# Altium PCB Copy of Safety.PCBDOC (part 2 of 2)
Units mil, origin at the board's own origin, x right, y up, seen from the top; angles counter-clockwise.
Board outline 11000 x 3900 mil, 4 copper layers (Top Layer, Grounds, +5V, Bottom Layer); 225 components, 170 nets, 779 pads, 129 vias.
Unrouted connection lines stored in the file: 11.
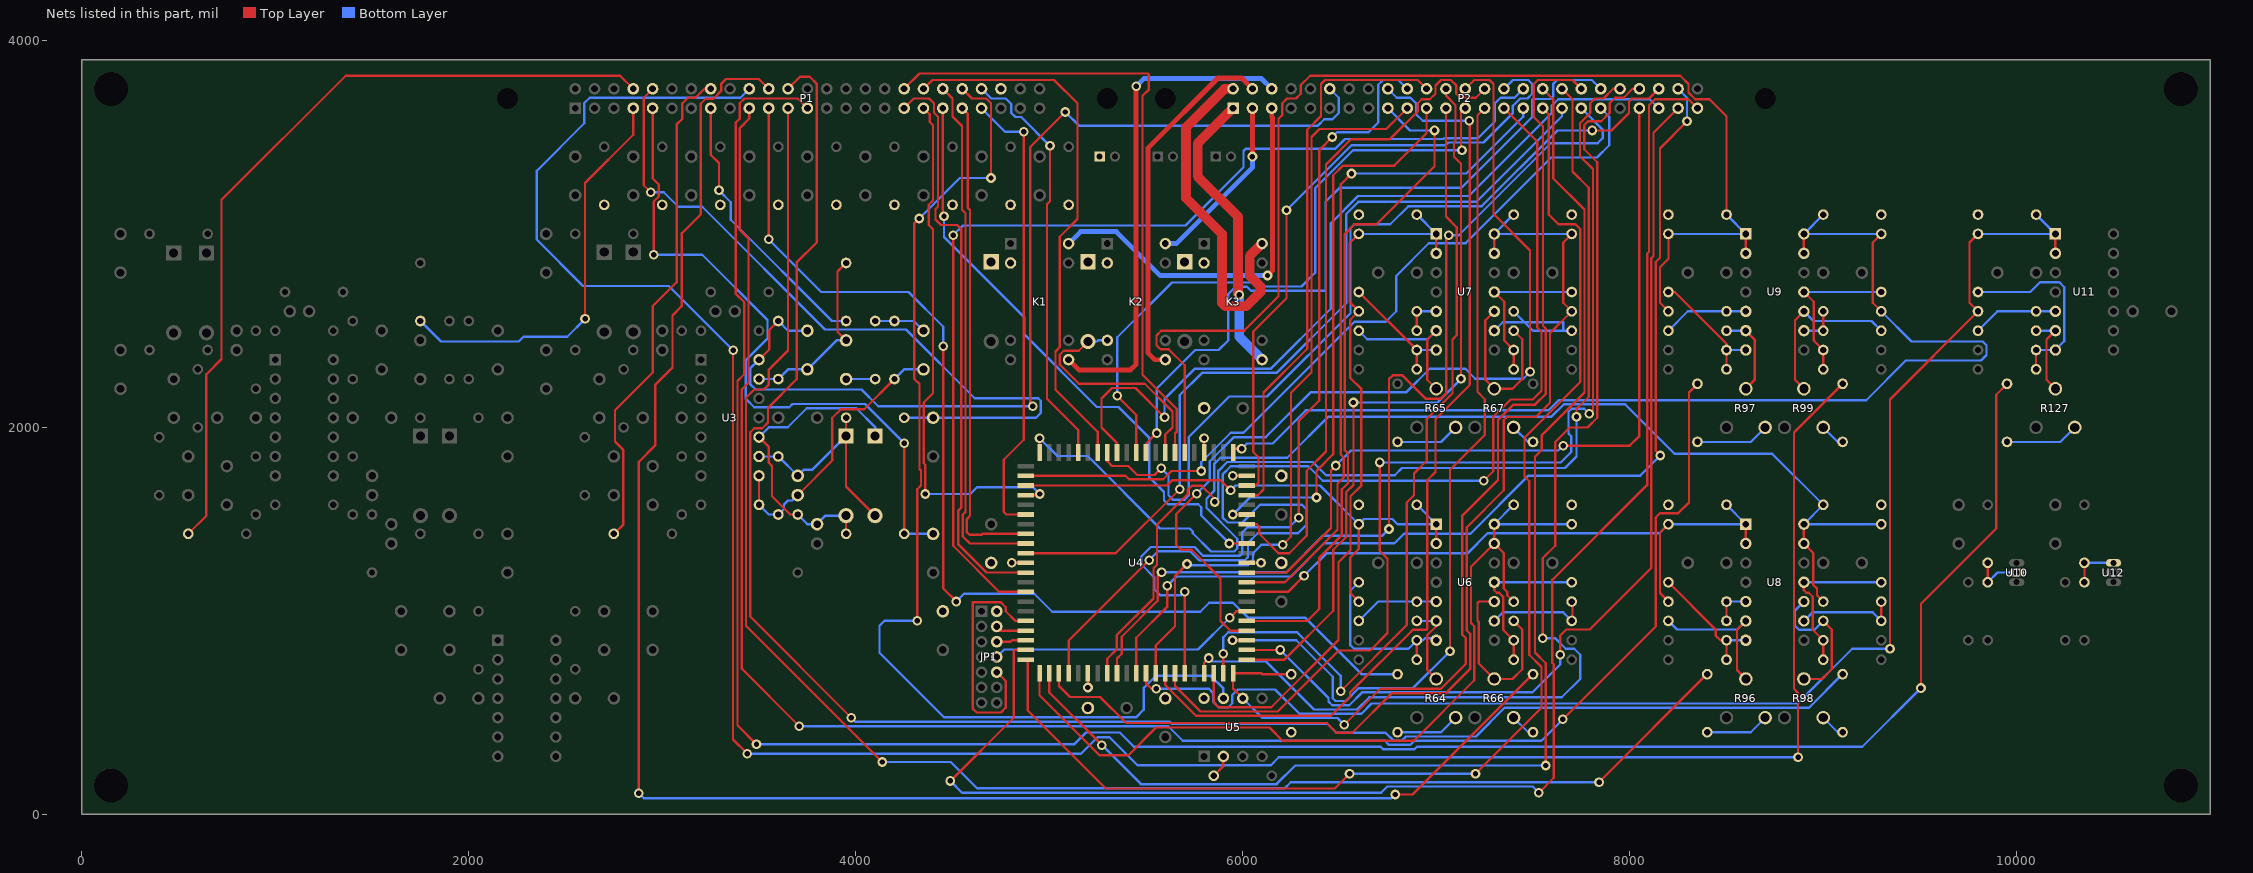
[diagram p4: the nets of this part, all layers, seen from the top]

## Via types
v1: diameter 50, hole 28, Top Layer to Bottom Layer, 129 vias

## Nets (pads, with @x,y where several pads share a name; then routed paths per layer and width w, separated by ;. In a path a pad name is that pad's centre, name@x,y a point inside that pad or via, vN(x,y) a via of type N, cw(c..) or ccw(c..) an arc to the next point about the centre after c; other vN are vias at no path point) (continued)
NetC36_1: C36.1 D7.2 D8.1 R34.1 R40.1 U3.9 | length 1144.7
  Top Layer w12: R40.1@3950,2050 D7.2@3950,1955.91 3950,1694.09 D8.1@4100,1544.09
  Bottom Layer w12: U3.9@3500,1850 R34.1@3600,1850 C36.1@3700,1750 3732,1782 3776.09,1782 D7.2@3950,1955.91
NetC36_2: C36.2 C44.1 R30.1 R34.2 R43.1 U3.8 | length 1473.9
  Top Layer w12: R30.1@3500,1600 U3.8@3500,1750 ; C36.2@3700,1650 3879,1829 3879,2050 3923,2094 4044,2094 R43.1@4200,2250
  Bottom Layer w12: R30.1@3500,1600 3550,1550 R34.2@3600,1550 3629.17,1579.17 3629.17,1601.41 3650,1622.25 3672.25,1622.25 C36.2@3700,1650 ; R43.1@4200,2250 4250,2300 C44.1@4350,2300
NetC37_1: C37.1 C40.2 R36.1 R41.2 U3.13 | length 969.3
  Top Layer w12: C40.2@3950,2450 3906,2494 3906,2806 R41.2@3950,2850
  Bottom Layer w12: U3.13@3500,2250 R36.1@3600,2250 3650,2300 C37.1@3750,2300 3900,2450 C40.2@3950,2450
NetC37_2: C37.2 P2.12 R36.2 U3.14 | length 5279.1
  Top Layer w12: U3.14@3500,2350 3553,2403 3553,2503 R36.2@3600,2550 ; v1(4915,2110) 4901,2124 4901,3448 v1(5083,3630)
  Bottom Layer w12: U3.14@3500,2350 3454,2304 3454,2225 3483,2196 4030.12,2196 4116.12,2110 v1(4915,2110) ; R36.2@3600,2550 3650,2500 C37.2@3750,2500 ; v1(5083,3630) 5153.16,3559.84 6388.58,3559.84 6421.58,3592.84 6463.84,3592.84 6496,3625 6496,3704 P2.12@6450,3750
NetC39_1: C39.1 D7.1 D8.2 R35.1 R39.1 U3.10 | length 1636.3
  Top Layer w12: U3.10@3500,1950 3551,1899 3551,1817.53 3567.53,1801 3567.53,1644.3 3661.83,1550 R35.1@3700,1550 ; R39.1@3950,1450 D7.1@3950,1544.09
  Bottom Layer w12: U3.10@3500,1950 3551,2001 3649,2001 3747,2099 4003,2099 4100,2002 D8.2@4100,1955.91 ; R35.1@3700,1550 3750,1500 C39.1@3800,1500 3844.09,1544.09 D7.1@3950,1544.09
NetC40_1: C40.1 R42.2 | length 150
  Bottom Layer w12: C40.1@3950,2250 R42.2@4100,2250
NetC42_1: C42.1 P1.9 R39.2 | length 3508.9
  Top Layer w12: P1.9@2950,3650 2950,3288 2982,3256 2982,3194.04 2956,3168.04 v1(2956,2892) ; R39.2@4250,1450 v1(4250,1919)
  Bottom Layer w12: v1(2956,2892) 3207,2892 3544,2555 3544,2460 3432,2348 3432,2147.47 3475,2104.47 3656.47,2104.47 3673,2121 4048,2121 v1(4250,1919) ; R39.2@4250,1450 C42.1@4400,1450
NetC43_1: C43.1 P1.10 R40.2 | length 3809.6
  Top Layer w12: v1(2941,3215) 2904,3252 2904,3704 P1.10@2950,3750
  Bottom Layer w12: v1(2941,3215) 3008,3215 3082.92,3140.08 3206.92,3140.08 3841,2506 4260,2506 4615,2151 4942.5,2151 4956,2137.5 4956,2075 4931,2050 C43.1@4400,2050 R40.2@4250,2050
NetC44_2: C44.2 R42.1 R43.2 | length 270.7
  Bottom Layer w12: R42.1@4100,2550 R43.2@4200,2550 4300,2550 C44.2@4350,2500
NetK1_8: K1.8 P2.6 | length 2559.5
  Top Layer w25: K1.8@5100,2350 5153,2297 5420,2297 5449,2326 v1(5449,3763)
  Bottom Layer w25: v1(5449,3763) 5489,3803 6097,3803 P2.6@6150,3750
NetK1_14: K1.14 P2.5 | length 2024.3
  Top Layer w25: v1(6128,2785) 6153,2810 6153,3603 6150,3606 P2.5@6150,3650
  Bottom Layer w25: K1.14@5100,2950 5162,3012 5347,3012 5574,2785 v1(6128,2785)
NetK2_8: K2.8 P2.4 | length 1876.2
  Top Layer w25: K2.8@5600,2350 5544.42,2350 5511,2383.42 5511,3445 5872,3806 5994,3806 P2.4@6050,3750
NetK2_14: K2.14 P2.3 | length 920
  Top Layer w25: v1(6050,3400) P2.3@6050,3650
  Bottom Layer w25: K2.14@5600,2950 5657.45,2950 6050,3342.55 v1(6050,3400)
NetK3_8: K3.8 P2.1 | length 1513.7
  Top Layer w50: P2.1@5950,3650 5767,3467 5767,3297.96 5975.47,3089.49 5975.47,2692.53 v1(5982,2686)
  Bottom Layer w50: v1(5982,2686) 5982,2468 K3.8@6100,2350
NetK3_14: K3.14 P2.2 | length 1847.3
  Top Layer w50: P2.2@5950,3750 5906,3750 5707,3551 5707,3186 5893,3000 5893,2643 5910,2626 6018,2626 6092,2700 6092,2728.47 6035.47,2785 6035.47,2885.47 K3.14@6100,2950
NetP1_7: P1.7 R16.1 | length 2135.5
  Top Layer w12: v1(2601,2561) 2601,3264 2850,3513 P1.7@2850,3650
  Bottom Layer w12: R16.1@1750,2550 1856,2444 2258,2444 2283,2469 2509,2469 v1(2601,2561)
NetP1_8: P1.8 R4.1 | length 4219.3
  Top Layer w12: R4.1@550,1450 644,1544 644,2275 722.37,2353.37 722.37,3176.37 1364,3818 2782,3818 P1.8@2850,3750
NetP1_15: P1.15 R41.1 | length 1432.7
  Top Layer w12: P1.15@3250,3650 3250,3409 3293,3366 v1(3293,3225)
  Bottom Layer w12: v1(3293,3225) 3354,3164 3354,3073 3877,2550 R41.1@3950,2550
NetP1_16: P1.16 R25.1 | length 2584.3
  Top Layer w12: R25.1@2750,1450 2799,1499 2799,1884 2756,1927 2756,2089 2951,2284 2951,2627 3074,2750 3074,3565 3104,3595 3104,3675 3133,3704 3172,3704 3218,3750 P1.16@3250,3750
NetP1_19: P1.19 R95.1 | length 9488.3
  Top Layer w12: P1.19@3450,3650 3450,3596.85 3401,3547.85 3401,3021 3445.48,2976.52 3445.48,2230.54 3410.47,2195.53 3410.47,753.53 v1(3708,456) ; v1(7654,491) 8134,971 8134,1534 8156,1556 8250,1556 8306,1612 8306,2181 R95.1@8350,2225
  Bottom Layer w12: v1(3708,456) 5615,456 5690,381 6734.44,381 6756,359.44 6865.56,359.44 6887.12,381 7544,381 v1(7654,491)
NetP1_20: P1.20 R111.1 | length 12644.1
  Top Layer w12: v1(3366,2399) 3366,387 v1(3440,313) ; v1(8870,295) 8870,628 8849,649 8849,1974 R111.1@9100,2225
  Bottom Layer w12: v1(3366,2399) 3033.91,2731.09 2590.91,2731.09 2351,2971 2351,3326 2597,3572 2597,3676 2625,3704 3404,3704 P1.20@3450,3750 ; v1(3440,313) 5164,313 5250,399 5311.5,399 5456.03,254.47 6146,254.47 6186.53,295 v1(8870,295)
NetP1_21: P1.21 R63.1 | length 5722.7
  Top Layer w12: v1(3550,2972) P1.21@3550,3650 ; v1(4452,2420) 4452,1168 v1(4520,1100)
  Bottom Layer w12: v1(3550,2972) 3822,2700 4272,2700 4452,2520 v1(4452,2420) ; v1(4520,1100) 4560,1140 4922.54,1140 5015.44,1047.1 5780.1,1047.1 5827,1094 5950,1094 6027,1017 6321.4,1017 6613.4,725 R63.1@6800,725
NetP1_22: P1.22 R78.1 | length 9039.1
  Top Layer w12: v1(2879,110) 2879,1823 2963,1907 2963,2220 3053,2310 3053,2579 3101,2627 3101,3003 3199,3101 3199,3673 3225,3699 3264.05,3699 3304,3738.95 3304,3775 3330,3801 3499,3801 P1.22@3550,3750 ; v1(6788,103) 6878,103 R78.1@7500,725
  Bottom Layer w12: v1(2879,110) 2905,84 6769,84 v1(6788,103)
NetP1_23: P1.23 R94.1 | length 8354.4
  Top Layer w12: P1.23@3650,3650 3650,2398 3551,2299 3551,2222 3525,2196 3475,2196 3432.47,2153.47 3432.47,975.53 v1(4136.95,271.05) ; v1(7841.61,166.61) R94.1@8400,725
  Bottom Layer w12: v1(4136.95,271.05) 4491.11,271.05 4627.72,134.44 6215.56,134.44 6247.73,166.61 v1(7841.61,166.61)
NetP1_24: P1.24 R110.1 | length 9163.2
  Top Layer w12: P1.24@3650,3750 3712,3812 3762,3812 3799,3775 3799,2957 3694.38,2852.38 3694.38,2249.38 3546,2101 3546,2025 3517,1996 3475,1996 3454.47,1975.47 3454.47,1022.53 v1(3977,500)
  Bottom Layer w12: v1(3977,500) 3997.48,479.52 5622.6,479.52 5633.11,469 6437,469 6484,422 6738,422 6778.56,381.44 6821.44,381.44 6843,403 7205,403 7353,551 8926,551 R110.1@9100,725
NetP1_25: P1.25 R126.1 | length 11742.6
  Top Layer w12: v1(3487,362) 3388.47,460.53 3388.47,2239.53 3423.48,2274.54 3423.48,2648 3379,2692.48 3379,3575 3400,3596 3400,3675 3425,3700 3700,3700 P1.25@3750,3650 ; v1(9505,653) 9505,1089 9894,1478 9894,2169 R126.1@9950,2225
  Bottom Layer w12: v1(3487,362) 5128,362 5189.39,423.39 5364,423.39 5437.39,350 6712.44,350 6725,337.44 6887.56,337.44 6900.12,350 9202,350 v1(9505,653)
NetP1_35: P1.35 U4.23 | length 2997.1
  Top Layer w12: P1.35@4250,3650 4300,3700 4379,3700 4404,3675 4404,3626.5 4425,3605.5 4425,3140.94 4412.5,3128.44 4412.5,3075 4441.06,3046.44 4523.56,3046.44 4545,3025 4545,1585.65 4530.22,1570.87 4530.22,1395.26 4675.49,1250 U4.23@4879.13,1250
NetP1_36: P1.36 U4.81 | length 3343.7
  Top Layer w12: P1.36@4250,3750 4329,3829 5510.02,3829 5515,3824.02 5515,3747 5482,3714 5482,2272 5659,2095 5659,1978.29 5650,1969.29 U4.81@5650,1870.87
NetP1_37: P1.37 U4.15 | length 2751.1
  Top Layer w12: P1.37@4350,3650 4382,3618 4382,3578.5 4399,3561.5 4399,3172.44 4377,3150.44 4377,3046.44 4399,3024.44 4399,2177 4351,2129 4351,1815 4359,1807 v1(4359,1656) ; U4.15@4879.13,1650 4945,1650 v1(4951,1656)
  Bottom Layer w12: v1(4359,1656) 4592,1656 4627,1691 4916,1691 v1(4951,1656)
NetP1_38: P1.38 U4.5 | length 2806.4
  Top Layer w12: P1.38@4350,3750 4396,3796 5025,3796 5146,3675 5146,3077 5054.47,2985.47 5054.47,2415 5032.47,2393 5032.47,2195 5250,1977.47 U4.5@5250,1870.87
NetP1_39: P1.39 U4.66 | length 3110.5
  Top Layer w12: P1.39@4450,3650 4450,3098 v1(4456,3092) ; v1(5931,1400) U4.66@6020.87,1400
  Bottom Layer w12: v1(4456,3092) 4456,2984 4871.59,2568.41 4871.59,2480.41 5246,2106 5357.84,2106 5516,1947.83 5516,1744 5593,1667 5593,1624 5614,1603 5770.5,1603 5786,1587.5 5786,1545 v1(5931,1400)
NetP1_40: P1.40 U4.20 | length 2709.5
  Top Layer w12: P1.40@4450,3750 4500,3700 4500,3607 4549,3558 4549,3125 4567,3107 4567,1563.65 4552.22,1548.87 4552.22,1437.5 4589.72,1400 U4.20@4879.13,1400
NetP1_41: P1.41 U4.19 | length 2528
  Top Layer w12: P1.41@4550,3650 4578,3622 4578,3136 4590.62,3123.38 4590.62,1543.27 4574.22,1526.87 4574.22,1458.15 4587.5,1444.87 4651.09,1444.87 4656.22,1450 U4.19@4879.13,1450
NetP1_42: P1.42 U5.7 | length 5628.6
  Top Layer w12: v1(4318,1001) 4318,1681 4337,1700 4337,1777 4329,1785 4329,2224.52 4301.52,2252 4301.52,3053.52 v1(4328,3080) ; P1.42@4550,3750 4600,3700 4674,3700 4699,3675 v1(4699,3289)
  Bottom Layer w12: v1(4318,1001) 4149,1001 4123,975 4123,836 4457.48,501.52 5448,501.52 5488,541.52 5488,654 5550,716 5834,716 5900,650 U5.7@5900,600 ; v1(4328,3080) 4537,3289 v1(4699,3289)
NetP1_43: P1.43 U4.17 | length 2395.9
  Top Layer w12: v1(4868,3528) 4868,1936 4764.83,1832.83 4764.83,1563.17 4778,1550 U4.17@4879.13,1550
  Bottom Layer w12: P1.43@4650,3650 4772,3528 v1(4868,3528)
NetP1_44: P1.44 U4.7 | length 2161
  Top Layer w12: v1(5004,3455) 5004,3169 4988,3153 4988,2148 5150,1986 U4.7@5150,1870.87
  Bottom Layer w12: P1.44@4650,3750 4700,3700 4775,3700 4804,3671 4804,3625 4825,3604 4855,3604 v1(5004,3455)
NetP2_17: P2.17 U4.58 | length 3487.8
  Top Layer w12: U4.58@6020.87,1000 6333,1000 6396,1063 6396,1327.23 6512.44,1443.67 6512.44,1680 6544,1711.56 6544,1866 6528,1882 6528,3000 6578,3050 6691,3050 6991,3350 v1(6991,3535)
  Bottom Layer w12: P2.17@6750,3650 6865,3535 v1(6991,3535)
NetP2_18: P2.18 U4.46 | length 4920
  Top Layer w12: U4.46@5600,729.13 5600,668.56 5758.56,510 6456.19,510 6554.19,608 6554.19,629.76 6879.32,954.89 6950.77,954.89 6954,958.11 6954,1727 6996,1769 6996,2042.1 7174,2220.1 7174,3582 v1(7171,3585)
  Bottom Layer w12: P2.18@6750,3750 6796,3704 6867,3704 6896,3675 6896,3619 6930,3585 v1(7171,3585)
NetP2_19: P2.19 U4.45 | length 3919.7
  Top Layer w12: U4.45@5550,729.13 5550,873 5650,973 5650,1232 v1(5712,1294) ; v1(6206,1393) 6248,1435 6248,1535 6249,1536 6249,2179 6355,2285 6355,3501 6396,3542 6742,3542 P2.19@6850,3650
  Bottom Layer w12: v1(5712,1294) 5719,1287 6025,1287 6053,1315 6053,1350 6096,1393 v1(6206,1393)
NetP2_20: P2.20 U4.48 | length 4476.5
  Top Layer w12: U4.48@5700,729.13 v1(5700,1150) ; v1(6290,1534) 6290,2035 6396,2141 6396,3434 v1(6463,3501)
  Bottom Layer w12: v1(5700,1150) 5682,1132 5575,1132 5543,1164 5543,1225 5475,1293 5475,1332.5 5524.5,1382 5750,1382 5796,1336 5984,1336 5998,1350 5998,1458 6024,1484 6240,1484 v1(6290,1534) ; v1(6463,3501) 6487.5,3525.5 6650,3525.5 6700,3575.5 6700,3771 6725,3796 6804,3796 P2.20@6850,3750
NetP2_21: P2.21 U4.69 | length 2943.4
  Top Layer w12: v1(5949,1550) U4.69@6020.87,1550 ; v1(6381,1638) 6381,1775 6468,1862 6468,3303.22 6517.78,3353 6783,3353 6950,3520 P2.21@6950,3650
  Bottom Layer w12: v1(5949,1550) 6037,1638 v1(6381,1638)
NetP2_22: P2.22 U4.71 | length 2890.9
  Top Layer w12: U4.71@6020.87,1650 6078,1650 6107,1679 6107,2181 6333,2407 6333,3539 6404,3610 6404,3775 6425,3796 6904,3796 P2.22@6950,3750
NetP2_23: P2.23 U4.52 | length 4260.1
  Top Layer w12: U4.52@5900,729.13 v1(5900,831) ; v1(6506,637) 6848,979 6848,1612 6885,1649 6885,1762 6951,1828 6951,2043.89 7084,2176.89 7084,2455 7106,2477 7106,3034 7050,3090 P2.23@7050,3650
  Bottom Layer w12: v1(5900,831) 5900,916 5925,941 6281,941 6506,716 v1(6506,637)
NetP2_24: P2.24 U4.54 | length 3816
  Top Layer w12: U4.54@6020.87,800 6215.59,800 6468,1052.41 6468,1367.82 6534.44,1434.26 6534.44,1665.56 6572,1703.12 v1(6572,2129) ; P2.24@7050,3750 7050,3715.05 7100,3665.05 7100,3480.93 7091.74,3472.68 7091.74,3398.93 7128,3362.68 v1(7128,2251)
  Bottom Layer w12: v1(6572,2129) 7006,2129 v1(7128,2251)
NetP2_25: P2.25 U4.1 | length 3320.8
  Top Layer w12: v1(5351,2163) 5450,2064 U4.1@5450,1870.87 ; v1(7133,3432) 7128,3437 7128,3628 P2.25@7150,3650
  Bottom Layer w12: v1(5351,2163) 5351,2466 5634,2749 6062.82,2749 6083.82,2728 6303,2728 6375,2800 6375,3237 6570,3432 v1(7133,3432)
NetP2_26: P2.26 U4.57 | length 4809.1
  Top Layer w12: v1(5762,1658) 5656.07,1552.07 5656.07,1393.22 5681.36,1367.92 5735.92,1367.92 5885,1218.85 5885,1000 5935,950 U4.57@6020.87,950 ; P2.26@7150,3750 7196,3796 7275,3796 7296,3775 7296,3104 7485,2915 v1(7485,2287)
  Bottom Layer w12: v1(5762,1658) 5830,1726 5830,1825 5955,1950 6119,1950 6350,2181 6844,2181 6966,2303 7151,2303 7202,2252 7450,2252 v1(7485,2287)
NetP2_27: P2.27 U4.56 | length 4412.3
  Top Layer w12: v1(5947,900) U4.56@6020.87,900 ; v1(7071,843.51) 7071,1781.37 7251,1961.37 7251,2146 7213,2184 7213,3613 P2.27@7250,3650
  Bottom Layer w12: v1(5947,900) 6276.93,900 6465,711.93 6465,600 6479,586 6533,586 6599.71,652.71 6880.2,652.71 v1(7071,843.51)
NetP2_28: P2.28 U4.68 | length 3522.9
  Top Layer w12: U4.68@6020.87,1500 6072.5,1500 6085,1487.5 6085,1450 6185,1350 6240,1350 6331,1441 6331,1776 6430,1875 6430,3359 6561,3490 6761,3490 6904,3633 6904,3675 6925,3696 6967,3696 6996,3725 6996,3767 7025,3796 7075,3796 7104,3767 7104,3725 7125,3704 7204,3704 P2.28@7250,3750
NetP2_29: P2.29 U4.36 | length 6116.6
  Top Layer w12: U4.36@5100,729.13 5100,898 v1(5516,1314) ; v1(7246,1724) 7295,1773 7295,2054.8 7384.83,2144.63 7498.75,2144.63 7544,2189.88 7544,2495.02 7522,2517.02 7522,3478 P2.29@7350,3650
  Bottom Layer w12: v1(5516,1314) 5562,1360 5728,1360 5774,1314 6010,1314 6027,1331 6027,1402 6078,1453 6286,1453 6331,1498 6331,1574.97 6304.97,1601 6090,1601 5998,1509 5922,1509 5896,1535 5896,1756.89 5938.11,1799 6339,1799 6414,1724 v1(7246,1724)
NetP2_30: P2.30 U4.72 | length 3321.7
  Top Layer w12: U4.72@6020.87,1700 6067.25,1700 6081,1713.75 6081,1845.74 6054,1872.74 6054,2496 6226,2668 v1(6226,3121.98)
  Bottom Layer w12: v1(6226,3121.98) 6562.02,3458 7047.74,3458 7062.74,3473 7244,3473 7396,3625 7396,3662 7434,3700 7471,3700 7496,3725 7496,3775 7475,3796 7396,3796 P2.30@7350,3750
NetP2_31: P2.31 U4.62 | length 3518.6
  Top Layer w12: U4.62@6020.87,1200 6218.32,1200 6490,1471.68 6490,1709.12 6522,1741.12 6522,1844 6506,1860 6506,3256 v1(6562,3312)
  Bottom Layer w12: v1(6562,3312) 7155.6,3312 7450,3606.4 P2.31@7450,3650
NetP2_32: P2.32 U4.25 | length 5442.4
  Top Layer w12: v1(4504,2994) 4504,1388 4742,1150 U4.25@4879.13,1150
  Bottom Layer w12: v1(4504,2994) 4554,3044 5703.73,3044 6003.95,3344.21 6003.95,3428 6016.95,3441 6479.02,3441 6529.02,3491 7036.74,3491 7040.74,3495 7216,3495 7303,3582 7303,3675 7332,3704 7404,3704 P2.32@7450,3750
NetP2_33: P2.33 U4.32 | length 6653.6
  Top Layer w12: U4.32@4879.13,800 4889,800 4889,537 5292,134 6476,134 v1(6552,210) ; v1(7203,210) 7544,551 7544,762 7481,825 7481,1722 7456,1747 7456,1947 7744,2235 7744,3025 7719,3050 7632,3050 7582,3100 7582,3618 P2.33@7550,3650
  Bottom Layer w12: v1(6552,210) v1(7203,210)
NetP2_34: P2.34 U4.34 | length 6617
  Top Layer w12: U4.34@5000,729.13 5000,630 v1(5272,358) ; P2.34@7550,3750 7604,3696 7604,3288 7766,3126 7766,2181 7546,1961 7546,1884.84 7510,1848.84 7510,837 7566,781 v1(7566,253)
  Bottom Layer w12: v1(5272,358) 5473.56,156.44 6175,156.44 6271.56,253 v1(7566,253)
NetP2_35: P2.35 U4.21 | length 4302.9
  Top Layer w12: U4.21@4879.13,1350 5343,1350 v1(5674,1681)
  Bottom Layer w12: v1(5674,1681) 5674,2167 5789,2282 6175,2282 6534.44,2641.44 6534.44,3103 6597,3165.56 7207,3165.56 7650,3608.56 P2.35@7650,3650
NetP2_36: P2.36 U4.40 | length 5402.9
  Top Layer w12: U4.40@5300,729.13 5300,804.53 5348.25,852.78 5348.25,925.48 5539,1116.23 5539,1272 5557,1290 5557,1497 5715,1655 5715,1676.5 5737.5,1699 5787.5,1699 5855,1631.5 v1(5855,1615) ; P2.36@7650,3750 7704,3696 7704,3323 7788,3239 7788,2159 7725,2096 v1(7725,2056)
  Bottom Layer w12: v1(5855,1615) 5874,1634 5874,1775.5 5919.5,1821 6362,1821 6430,1753 6786,1753 6823,1790 7665,1790 7725,1850 v1(7725,2056)
NetP2_37: P2.37 U4.41 | length 5051.6
  Top Layer w12: U4.41@5350,729.13 5350,806.41 5374.37,830.78 5374.37,918.37 5561,1105 5561,1232 v1(5580.52,1251.52) ; v1(6756,1475) 6756,2250 6775,2269 6825,2269 6945,2149 7025,2149 7051,2175 7051,2979 v1(7065,2993)
  Bottom Layer w12: v1(5580.52,1251.52) 6225,1251.52 6414.48,1441 6722,1441 v1(6756,1475) ; v1(7065,2993) 7116,2993 7592,3469 7834,3469 7860,3495 7860,3540 P2.37@7750,3650
NetP2_38: P2.38 R49.1 U4.53 U5.6 | length 5340.5
  Top Layer w12: U5.6@6000,600 5950,650 U4.53@5950,729.13 6097,729.13 6101.13,725 R49.1@6250,725 ; v1(6525,463) 6711,649 7025,649 7153,777 7153,911 7135,929 7135,1545 7319,1729 7319,2038.11 7398.89,2118 7511,2118 7566,2173 7566,2511 7551.52,2525.48 7551.52,3556.48 7504,3604 7504,3775 7525,3796 7704,3796 P2.38@7750,3750
  Bottom Layer w12: U5.6@6000,600 6102,498 6490,498 v1(6525,463)
NetP2_39: P2.39 U4.13 | length 4080.6
  Top Layer w12: U4.13@4879.13,1750 5394,1750 5412,1732 5589.24,1732 5632.24,1775 v1(5785,1775)
  Bottom Layer w12: v1(5785,1775) 5785,1819.62 5937.5,1972.12 6004.12,1972.12 6578,2546 6739,2546 6793,2600 6793,2783 6961.71,2951.71 7151.71,2951.71 7594.76,3394.76 7830.35,3394.76 7894,3458.41 7894,3606 P2.39@7850,3650
NetP2_40: P2.40 U4.84 | length 3842.5
  Top Layer w12: U4.84@5500,1870.87 5500,1916 v1(5555,1971)
  Bottom Layer w12: v1(5555,1971) 5555,2200 5755,2400 5875,2400 5925,2450 5925,2690 5962,2727 6022,2727 6043,2706 6425,2706 6428,2709 6428,3166 6500,3238 7129.33,3238 7496,3604.67 7496,3693 7500,3697 7590.92,3697 7604,3710.08 7604,3775 7625,3796 7804,3796 P2.40@7850,3750
NetP2_42: P2.42 U4.47 | length 5482.1
  Top Layer w12: U4.47@5650,729.13 5650,664 5782,532 6181,532 6496,847 6658.63,847 6748.48,936.85 6748.48,1321.52 6708,1362 v1(6708,1819) ; v1(7791,2071) 7810,2090 7810,3335 7743,3402 7743,3572 7796,3625 7796,3675 7821,3700 7865.05,3700 7915.05,3750 P2.42@7950,3750
  Bottom Layer w12: v1(6708,1819) 7644,1819 7698,1873 7698,1954 7684,1968 7684,2081 7700,2097 7765,2097 v1(7791,2071)
NetP2_43: P2.43 U4.63 | length 4189.8
  Top Layer w12: U4.63@6020.87,1250 6225.5,1250 6456,1480.5 6456,1778 v1(6481,1803) ; v1(7656,1906) 8000,1906 8050,1956 P2.43@8050,3650
  Bottom Layer w12: v1(6481,1803) 6559,1881 7631,1881 v1(7656,1906)
NetP2_44: P2.44 U4.50 | length 5779
  Top Layer w12: U4.50@5800,729.13 5800,783 v1(5825,808) ; v1(7551,911) 7551,1325 7615,1389 7615,1925 7690,2000 7782,2000 7832,2050 7832,3371 7765,3438 7765,3562.5 7784.5,3582 7853,3582 7896,3625 7896,3675 7925,3704 7969.05,3704 8015.05,3750 P2.44@8050,3750
  Bottom Layer w12: v1(5825,808) 5843,790 6120,790 6368,542 6591,542 6654,605 7649,605 7744,700 7744,825 7713,856 7669,856 7614,911 v1(7551,911)
NetP2_45: P2.45 U4.3 | length 4311.7
  Top Layer w12: U4.3@5350,1870.87 5350,1920 5270,2000 5270,2149 5325,2204 5445,2204 v1(5596,2053)
  Bottom Layer w12: v1(5596,2053) 5596,2147 5753,2304 6146,2304 6455,2613 6455,3054.67 6596.33,3196 7168,3196 7596,3624 7596,3661.05 7630.95,3696 8104,3696 P2.45@8150,3650
NetP2_46: P2.46 U4.4 | length 4414.9
  Top Layer w12: U4.4@5300,1870.87 5300,1826 5325,1801 5408,1801 5455,1754 5544,1754 v1(5579,1789) ; v1(7806,3535) 7906,3535 7996,3625 7996,3683.95 8012.05,3700 8100,3700 P2.46@8150,3750
  Bottom Layer w12: v1(5579,1789) 5616,1752 5616,1649.5 5638.5,1627 5700,1627 5721,1648 5721,1951 5930,2160 6126,2160 6556.44,2590.44 6556.44,3029.44 6577,3050 6762.44,3050 6856,3143.56 7234.56,3143.56 7626,3535 v1(7806,3535)
NetP2_47: P2.47 U4.55 | length 5034.4
  Top Layer w12: U4.55@6020.87,850 v1(6194,850) ; v1(7641,825) 7641,925 7672,956 7793,956 8112,1275 8112,2874.85 8123,2885.85 8123,3523 P2.47@8250,3650
  Bottom Layer w12: v1(6194,850) 6443,601 6443,583.5 6462.5,564 6550,564 6616.71,630.71 7496.71,630.71 7641,775 v1(7641,825)
NetP2_48: P2.48 U4.43 | length 5337
  Top Layer w12: U4.43@5450,729.13 5450,912.76 5609,1071.76 v1(5609,1181) ; v1(8158,1855) 8134,1879 8134,2855 8156,2877 8156,3442 v1(8296,3582)
  Bottom Layer w12: v1(5609,1181) 5657.52,1229.52 6250,1229.52 6421.48,1401 6784,1401 6834,1451 7177,1451 7477,1751 8054,1751 v1(8158,1855) ; P2.48@8250,3750 8296,3704 v1(8296,3582)
NetP2_49: P2.49 U4.31 | length 8042
  Top Layer w12: v1(4489,173) 4816,500 4816,845 4821,850 U4.31@4879.13,850 ; v1(7530.44,112.44) 7607,189 7607,777 7600,784 7600,1212 8090,1702 8090,2897.85 8100,2907.85 8100,3665.05 8130.95,3696 8304,3696 P2.49@8350,3650
  Bottom Layer w12: v1(4489,173) 4549.56,112.44 6715.04,112.44 6747.21,144.61 7498.27,144.61 v1(7530.44,112.44)
NetR48_1: R48.1 U5.2 | length 120.7
  Top Layer w12: R48.1@5850,200 5900,250 U5.2@5900,300
NetR50_1: R50.1 R51.2 R54.1 U7.7 | length 624.3
  Top Layer w12: R54.1@6600,2700 R51.2@6900,2400 R50.1@6900,2300
  Bottom Layer w12: R51.2@6900,2400 U7.7@7000,2400
NetR52_1: R52.1 R65.3 U7.6 | length 774.6
  Top Layer w12: R65.3@7000,2200 6954,2246 6954,2454 U7.6@7000,2500
  Bottom Layer w12: R52.1@6600,2500 6644,2456 6956,2456 U7.6@7000,2500
NetR52_2: R52.2 R53.1 U7.5 | length 200
  Top Layer w12: R52.2@6900,2500 R53.1@6900,2600
  Bottom Layer w12: R53.1@6900,2600 U7.5@7000,2600
NetR53_2: R53.2 R54.2 R61.2 U4.51 U7.1 U7.2 | length 3819.8
  Top Layer w12: U4.51@5850,729.13 5850,579 5875,554 6147,554 6494.65,901.65 6494.65,1303.65 6556.44,1365.44 6556.44,1644 6613,1700.56 6613,2199 6556,2256 6556,2556 R53.2@6600,2600 6551.63,2648.37 6551.63,2951.63 R54.2@6600,3000 ; U7.2@7000,2900 U7.1@7000,3000
  Bottom Layer w12: R54.2@6600,3000 U7.1@7000,3000 R61.2@6900,3100
NetR55_1: R55.1 R56.2 R59.1 U6.7 | length 921.6
  Top Layer w12: R55.1@6900,800 R56.2@6900,900
  Bottom Layer w12: R59.1@6600,1200 6556,1156 6556,875 6575,856 6856,856 R56.2@6900,900 6931.5,900 6941.5,910 6990,910 U6.7@7000,900
NetR57_1: R57.1 R64.3 U6.6 | length 438.1
  Top Layer w12: R64.3@7000,700 6954,746 6954,927 7000,973 U6.6@7000,1000
  Bottom Layer w12: R57.1@6900,1000 U6.6@7000,1000
NetR57_2: R57.2 R58.1 U6.5 | length 441.4
  Bottom Layer w12: R57.2@6600,1000 6700,1100 R58.1@6900,1100 U6.5@7000,1100
NetR58_2: R58.2 R59.2 R60.2 U4.14 U6.1 U6.2 | length 2947.5
  Top Layer w12: U4.14@4879.13,1700 5609,1700 5636.77,1727.77 5884.23,1727.77 v1(5937,1675) ; R58.2@6600,1100 6556,1144 6556,1328 6600,1372 R59.2@6600,1500 ; U6.2@7000,1400 U6.1@7000,1500
  Bottom Layer w12: v1(5937,1675) 5962,1700 6400,1700 R59.2@6600,1500 6626.83,1526.83 6773.17,1526.83 6800,1500 U6.1@7000,1500 R60.2@6900,1600
NetR62_2: R62.2 R65.2 | length 331.1
  Bottom Layer w12: R62.2@6800,1925 7025,1925 R65.2@7100,2000
NetR63_2: R63.2 R64.2 | length 331.1
  Bottom Layer w12: R63.2@6800,425 7025,425 R64.2@7100,500
NetR66_2: R66.2 R78.2 | length 131.1
  Bottom Layer w12: R66.2@7400,500 7475,425 R78.2@7500,425
NetR66_3: R66.3 R70.1 U6.10 | length 951.3
  Top Layer w12: U6.10@7300,1100 7221,1100 7213,1092 7213,1001 7219,995 7219,781 R66.3@7300,700 7394,700 7444,750 7444,956 R70.1@7400,1000
NetR67_2: R67.2 R79.2 | length 131.1
  Bottom Layer w12: R67.2@7400,2000 7475,1925 R79.2@7500,1925
NetR67_3: R67.3 R75.1 U7.10 | length 871
  Top Layer w12: U7.10@7300,2600 7254,2554 7254,2246 R67.3@7300,2200 7394,2200 7444,2250 7444,2456 R75.1@7400,2500
NetR68_1: R68.1 R69.2 R80.1 U6.11 | length 848.7
  Top Layer w12: U6.11@7300,1200 7300,1158.03 7312.5,1145.53 7325,1145.53 7345.53,1125 7345.53,954.47 R69.2@7400,900 R68.1@7400,800
  Bottom Layer w12: U6.11@7300,1200 R80.1@7700,1200
NetR70_2: R70.2 R71.1 U6.9 | length 539.6
  Top Layer w12: R70.2@7700,1000 7703.79,1003.79 7703.79,1096.21 R71.1@7700,1100
  Bottom Layer w12: U6.9@7300,1000 7344,1044 7656,1044 R70.2@7700,1000
NetR71_2: R71.2 R72.2 R80.2 U4.33 U6.13 U6.14 | length 4452.7
  Top Layer w12: U4.33@4950,729.13 4950,616 5261,305 5408,305 5552,449 6138,449 6206,381 6885.13,381 7197,692.87 7197,973 7180,990 7180,1280 U6.13@7300,1400 ; U6.14@7300,1500 U6.13@7300,1400 ; R71.2@7400,1100 7367.53,1132.47 7367.53,1149 7349,1167.53 7349,1351 U6.13@7300,1400
  Bottom Layer w12: R72.2@7400,1600 U6.14@7300,1500 R80.2@7700,1500
NetR73_1: R73.1 R74.2 R81.1 U7.11 | length 841.4
  Top Layer w12: U7.11@7300,2700 7351,2649 7351,2449 R74.2@7400,2400 R73.1@7400,2300
  Bottom Layer w12: U7.11@7300,2700 R81.1@7700,2700
NetR75_2: R75.2 R76.1 U7.9 | length 759.6
  Bottom Layer w12: U7.9@7300,2500 7344,2544 7456,2544 ; R76.1@7400,2600 7456,2544 ; R75.2@7700,2500 7656,2500 ; 7456,2544 7500,2500 7656,2500 ; 7456,2544 7656,2544 7656,2500
NetR76_2: R76.2 R77.2 R81.2 U4.35 U7.13 U7.14 | length 5671.9
  Top Layer w12: U4.35@5050,729.13 5050,664 5107,607 5263,607 5398,472 6434,472 6484,422 6566,422 6771,627 7050,627 7175,752 7175,933.5 7157.5,951 7157.5,1483.5 7349,1675 7349,2037 7365.78,2053.78 7514.28,2053.78 7588,2127.5 7588,2488 R76.2@7700,2600 7656,2644 7656,2956 R81.2@7700,3000 ; U7.13@7300,2900 U7.14@7300,3000
  Bottom Layer w12: R77.2@7400,3100 U7.14@7300,3000 R81.2@7700,3000
NetR82_1: R82.1 R97.3 U9.6 | length 437.7
  Top Layer w12: R97.3@8600,2200 8645.53,2245.53 8645.53,2454.47 U9.6@8600,2500
  Bottom Layer w12: R82.1@8500,2500 U9.6@8600,2500
NetR82_2: R82.2 R83.1 U9.5 | length 441.4
  Bottom Layer w12: R82.2@8200,2500 8300,2600 R83.1@8500,2600 U9.5@8600,2600
NetR83_2: R83.2 R92.2 R93.2 U4.80 U9.1 U9.2 | length 6488.8
  Top Layer w12: U4.80@5700,1870.87 5700,2321 5617,2404 5575,2404 5554,2425 5554,2475 5579,2500 6007,2500 6185,2678 6185,3595 6204,3614 6204,3675 6229,3700 6275,3700 6300,3725 6300,3769 6349,3818 8261,3818 8304,3775 8304,3730.95 8338.95,3696 8412,3696 8500,3608 R93.2@8500,3100 ; R83.2@8200,2600 8156,2644 8156,2828 8200,2872 R92.2@8200,3000 ; U9.2@8600,2900 U9.1@8600,3000
  Bottom Layer w12: R92.2@8200,3000 U9.1@8600,3000 R93.2@8500,3100
NetR84_1: R84.1 R85.2 R88.1 U8.7 | length 642.4
  Top Layer w12: R88.1@8200,1200 8444,956 8444,925 8469,900 R85.2@8500,900 R84.1@8500,800
  Bottom Layer w12: R85.2@8500,900 U8.7@8600,900
NetR86_1: R86.1 R96.3 U8.6 | length 774.6
  Top Layer w12: R96.3@8600,700 8554,746 8554,954 U8.6@8600,1000
  Bottom Layer w12: R86.1@8200,1000 8244,956 8556,956 U8.6@8600,1000
NetR86_2: R86.2 R87.1 U8.5 | length 200
  Top Layer w12: R86.2@8500,1000 R87.1@8500,1100
  Bottom Layer w12: R87.1@8500,1100 U8.5@8600,1100
NetR87_2: R87.2 R88.2 R89.2 U4.61 U8.1 U8.2 | length 3402
  Top Layer w12: U4.61@6020.87,1150 6234,1150 v1(6317,1233) ; R87.2@8200,1100 8156,1144 8156,1456 R88.2@8200,1500 ; U8.2@8600,1400 U8.1@8600,1500
  Bottom Layer w12: v1(6317,1233) 6433,1349 7161,1349 7265,1453 8153,1453 R88.2@8200,1500 U8.1@8600,1500 R89.2@8500,1600
NetR90_1: R90.1 R91.2 R92.1 U9.7 | length 643.3
  Top Layer w12: R92.1@8200,2700 8232.5,2700 8500,2432.5 R91.2@8500,2400 R90.1@8500,2300
  Bottom Layer w12: R91.2@8500,2400 U9.7@8600,2400
NetR94_2: R94.2 R96.2 | length 331.1
  Bottom Layer w12: R94.2@8400,425 8625,425 R96.2@8700,500
NetR95_2: R95.2 R97.2 | length 381.1
  Bottom Layer w12: R95.2@8350,1925 8625,1925 R97.2@8700,2000
NetR98_2: R98.2 R110.2 | length 131.1
  Bottom Layer w12: R98.2@9000,500 9075,425 R110.2@9100,425
NetR98_3: R98.3 R102.1 U8.10 | length 750.4
  Top Layer w12: R98.3@8900,700 8994,700 9044,750 9044,956 R102.1@9000,1000
  Bottom Layer w12: U8.10@8900,1100 8854,1054 8854,975 8874.53,954.47 8954.47,954.47 R102.1@9000,1000
NetR99_2: R99.2 R111.2 | length 131.1
  Bottom Layer w12: R99.2@9000,2000 9075,1925 R111.2@9100,1925
NetR99_3: R99.3 R107.1 U9.10 | length 879.5
  Top Layer w12: R99.3@8900,2200 8854,2246 8854,2554 U9.10@8900,2600
  Bottom Layer w12: U9.10@8900,2600 8950,2550 9250,2550 R107.1@9300,2500
NetR100_1: R100.1 R101.2 R112.1 U8.11 | length 849
  Top Layer w12: U8.11@8900,1200 8900,1158.03 8912.5,1145.53 8925.47,1145.53 8946,1125 8946,954 R101.2@9000,900 R100.1@9000,800
  Bottom Layer w12: U8.11@8900,1200 R112.1@9300,1200
NetR102_2: R102.2 R103.1 U8.9 | length 536.5
  Top Layer w12: R102.2@9300,1000 R103.1@9300,1100
  Bottom Layer w12: U8.9@8900,1000 8944,1044 9256,1044 R102.2@9300,1000
NetR103_2: R103.2 R104.2 R112.2 U4.11 U8.13 U8.14 | length 6341.2
  Top Layer w12: U4.11@4950,1870.87 v1(4950,1944) ; U8.14@8900,1500 U8.13@8900,1400 8949,1351 8949,1186.06 8967.53,1167.53 8967.53,1132.47 R103.2@9000,1100
  Bottom Layer w12: v1(4950,1944) 5042,1852 5198.66,1852 5572.66,1478 5726.5,1478 5742,1462.5 5742,1453 5836,1359 5956,1359 5972,1375 5972,1425 5812.5,1584.5 5812.5,1631.5 5852,1671 5852,1810.56 5884.44,1843 6230,1843 6443,2056 7595.49,2056 7658.49,2119 7976.97,2119 8231.97,1864 8736,1864 R104.2@9000,1600 U8.14@8900,1500 R112.2@9300,1500
NetR105_1: R105.1 R106.2 R113.1 U9.11 | length 841.4
  Top Layer w12: U9.11@8900,2700 8951,2649 8951,2449 R106.2@9000,2400 R105.1@9000,2300
  Bottom Layer w12: U9.11@8900,2700 R113.1@9300,2700
NetR107_2: R107.2 R108.1 U9.9 | length 200
  Top Layer w12: R107.2@9000,2500 R108.1@9000,2600
  Bottom Layer w12: U9.9@8900,2500 R107.2@9000,2500
NetR108_2: R108.2 R109.2 R113.2 U4.75 U9.13 U9.14 | length 5857.8
  Top Layer w12: U4.75@5950,1870.87 5950,1889 v1(5994,1889) ; U9.13@8900,2900 U9.14@8900,3000 ; R108.2@9300,2600 9256,2644 9256,2956 R113.2@9300,3000
  Bottom Layer w12: v1(5994,1889) 6022.34,1917.34 6155.34,1917.34 6326,2088 7579.39,2088 7632.39,2141 9222,2141 9427,2346 9815,2346 9844,2375 9844,2425 9825,2444 9456,2444 R108.2@9300,2600 ; R109.2@9000,3100 U9.14@8900,3000 R113.2@9300,3000
NetR115_1: R115.1 R116.1 U10.2 | length 270.7
  Top Layer w12: R115.1@9850,1200 R116.1@9850,1300
  Bottom Layer w12: R115.1@9850,1200 9900,1250 U10.2@10000,1250
NetR117_1: R117.1 R118.2 R121.1 U11.7 | length 1021.1
  Top Layer w12: R117.1@10100,2300 R118.2@10100,2400
  Bottom Layer w12: R121.1@9800,2700 10070,2700 10120,2750 10221,2750 10246,2725 10246,2446 U11.7@10200,2400 R118.2@10100,2400
NetR119_1: R119.1 R127.3 U11.6 | length 438.1
  Top Layer w12: R127.3@10200,2200 10154,2246 10154,2454 U11.6@10200,2500
  Bottom Layer w12: R119.1@10100,2500 U11.6@10200,2500
NetR119_2: R119.2 R120.1 U11.5 | length 441.4
  Bottom Layer w12: R119.2@9800,2500 9900,2600 R120.1@10100,2600 U11.5@10200,2600
NetR120_2: R120.2 R121.2 R122.2 U4.44 U11.1 U11.2 | length 7238.9
  Top Layer w12: U4.44@5500,729.13 5500,677 5528,649 v1(5553,649) ; v1(9345,856) 9345,2145 R120.2@9800,2600 9756,2644 9756,2956 R121.2@9800,3000 ; U11.2@10200,2900 U11.1@10200,3000
  Bottom Layer w12: v1(5553,649) 5825,649 5846,628 5846,583 5875,554 5925,554 5946,575 5946,617 5975,646 6167,646 6293,520 6613,520 6666,573 8867,573 9150,856 v1(9345,856) ; R121.2@9800,3000 U11.1@10200,3000 R122.2@10100,3100
NetR124_1: R124.1 R125.1 U12.1 | length 250
  Top Layer w12: R124.1@10350,1200 R125.1@10350,1300
  Bottom Layer w12: R125.1@10350,1300 U12.1@10500,1300
NetR126_2: R126.2 R127.2 | length 381.1
  Bottom Layer w12: R126.2@9950,1925 10225,1925 R127.2@10300,2000
TCK: JP1.6 U4.30 | length 153.5
  Top Layer w12: JP1.6@4728.74,892.52 4800,892.52 4807.48,900 U4.30@4879.13,900
TDI: JP1.10 U4.28 | length 1267.5
  Top Layer w12: JP1.10@4728.74,735.04 4775,688.78 4775,552 4750,527 4625,527 4604,548 4604,1096 4750,1096 4775,1071 4775,1050 4825,1000 U4.28@4879.13,1000
TDO: JP1.8 U4.59 | length 1390
  Top Layer w12: v1(5933,1016) 5967,1050 U4.59@6020.87,1050
  Bottom Layer w12: JP1.8@4728.74,813.78 4766.96,852 5769,852 v1(5933,1016)
TEL_ENABLE: D10.1 K2.6 U4.82 | length 1237
  Top Layer w12: D10.1@5200,2444.09 5151.91,2396 5075,2396 5054.47,2375.47 5054.47,2324.53 5153,2226 5493.29,2226 5637,2082.29 5637,2000 5600,1963 U4.82@5600,1870.87
  Bottom Layer w12: D10.1@5200,2444.09 5247,2444.09 5252.91,2450 K2.6@5300,2450
TMS: JP1.4 U4.29 | length 159.2
  Top Layer w12: JP1.4@4728.74,971.26 4750,950 U4.29@4879.13,950
VCC: C46.1 C47.1 C50.1 C51.1 C52.1 C54.1 C56.1 C57.1 D9.2 D10.2 D11.2 JP1.2 K1.2 K2.2 K3.2 P1.46 R24.2 R27.2 R33.2 R37.2 R38.2 R44.2 R45.2 R46.2 R47.2 R49.2 R60.1 R61.1 R72.1 R77.1 R89.1 R93.1 R104.1 R109.1 R122.1 U4.22 U4.38 U4.64 U4.73 U4.78 U5.8 | length 366.5
  Top Layer w12: v1(4805.83,1300) U4.22@4879.13,1300 ; v1(5200,655.83) U4.38@5200,729.13 ; U4.78@5800,1870.87 v1(5800,1944.17) ; v1(5947.56,1750) U4.73@6020.87,1750 ; U4.64@6020.87,1300 v1(6094.17,1300)
pads on no net: JP1.12 JP1.14 K1.1 K1.7 K1.9 K1.13 K2.1 K2.7 K2.9 K2.13 K3.1 K3.7 K3.9 K3.13 P1.0 P1.45 P2.0 P2.7 P2.16 P2.41 P2.50 U2.7 U2.8 U4.9 U4.10 U4.12 U4.24 U4.74 U4.76 U4.77 U5.1 U5.5 U10.3 U11.13 U11.14 U12.3

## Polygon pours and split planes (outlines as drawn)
GND on Grounds (split plane): 4385.02,304.15 4554.15,135.01 6320.85,135.01 6389.98,204.15 6389.98,3045.85 6345.85,3089.98 5600,3089.98 cw(c5600,3100) 5592.92,3092.92 5467.92,3217.92 cw(c5475,3225) 5464.98,3225 5464.98,3420.85 5370.85,3514.98 4925,3514.98 cw(c4925,3525) 4917.92,3517.92 4892.92,3542.92 cw(c4900,3550) 4889.98,3550 4889.98,3689.98 4810.02,3689.98 4810.02,3600 cw(c4800,3600) 4807.08,3592.92 4707.08,3492.92 cw(c4700,3500) 4700,3489.98 2454.15,3489.98 2410.01,3445.85 2410.01,3204.15 2529.15,3085.02 4525,3085.02 cw(c4525,3075) 4532.08,3082.08 4607.08,3007.08 cw(c4600,3000) 4610.02,3000 4610.02,1300 cw(c4600,1300) 4607.08,1292.92 4385.02,1070.85
AGND on Grounds (split plane): 20.02,20.01 20.02,3879.98 10979.99,3879.98 10979.99,20.01
VCC on +5V (split plane): 20.02,20.01 20.02,3879.98 10979.99,3879.98 10979.99,20.01

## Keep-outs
Keep-Out Layer:
  lines w10: 50,300 300,300 300,50 10700,50 10700,300 10950,300 10950,3600 10700,3600 10700,3850 300,3850 300,3600 50,3600 50,300

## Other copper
Grounds (plane layer: these items are gaps in the copper):
  lines w20: 2400,3200 2525,3075 4525,3075 4600,3000 4600,1300 4375,1075 4375,300 4550,125 6325,125 6400,200 6400,3050 6350,3100 5600,3100 5475,3225 5475,3425 5375,3525 4925,3525 4900,3550 4900,3700 4800,3700 4800,3600 4700,3500 2450,3500 2400,3450 2400,3200

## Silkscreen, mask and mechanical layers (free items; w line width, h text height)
Top Overlay:
  text "TCS3-Safety" at 500,425 h60
  text "IRTF" at 500,325 h60
  text "Rev. -" at 500,225 h60
  text "3/2005" at 500,125 h60
Mechanical 1:
  the board outline again, w20
Mechanical 16:
  lines w5: -1295,-70 -1095,-70 ; -1295,2305 -1095,2305 ; -1295,4680 -1095,4680 ; 1205,-2445 1205,-2245 ; 1205,6855 1205,7055 ; 3705,-2445 3705,-2245 ; 3705,6855 3705,7055 ; 6205,-2445 6205,-2245 ; 8705,-2445 8705,-2245 ; 9005,-1940 13505,-1940 ; 9005,-1640 10505,-1640 ; 10505,-2240 10505,-1640 ; 11205,-2445 11205,-2245 ; 11205,6855 11205,7055 ; 11905,-2240 11905,-1940 ; 12605,-2240 12605,-1940 ; 13505,-70 13705,-70 ; 13505,2305 13705,2305 ; 13505,4680 13705,4680 ; 10505,-1640 10505,-1340 ; 10505,-1340 13505,-1340 13505,-2240 9005,-2240 9005,-1340 10505,-1340 ; -1295,-2445 -1295,7055 13705,7055 13705,-2445 -1295,-2445 ; -1095,-2245 -1095,6855 13505,6855 13505,-2245 -1095,-2245
  lines w10: -120,60 -100,0 ; -120,3840 -100,3900 ; -110,0 -90,0 ; -110,3900 -90,3900 ; -100,1669.09 -100,0 ; -100,2230.91 -100,3900 ; -80,60 -100,0 ; -80,3840 -100,3900 ; 0,-110 0,-90 ; 60,-120 0,-100 ; 60,-80 0,-100 ; 5199.09,-100 0,-100 ; 5800.91,-100 11000,-100 ; 10940,-120 11000,-100 ; 10940,-80 11000,-100 ; 11000,-110 11000,-90
  lines w11: 11210,2655.5 13190,2655.5 ; 11210,2863.3 13190,2863.3 ; 11150,1617 ccw(c11217,1617) 11217,1550 13183,1550 ccw(c13183,1617) 13250,1617 13250,3133 ccw(c13183,3133) 13183,3200 11217,3200 ccw(c11217,3133) 11150,3133 11150,1617
  text "1" at -63.66,6925 h70
  text "2" at 2432,6925 h70
  text "3" at 4921.34,6925 h70
  text "6" at 12432,6925 h70
  text "A" at -1220,5782 h70
  text "A" at 13580,5782 h70
  text "B" at -1220,3402 h70
  text "B" at 13580,3402 h70
  text "Layer Stack Up Detail for: Safety.PCBDOC" at 11210,2998.75 h48
  text "Layer" at 11210,2785.8 h48
  text "Name" at 11210,2689.8 h48
  text "Top Layer" at 11210,2481.25 h67
  text "Grounds" at 11210,2256.25 h67
  text "+5V" at 11210,2031.25 h67
  text "Bottom Layer" at 11210,1806.25 h67
  text "3900 (mil)" at -64.01,1679.09 h60 r90
  text "C" at -1220,1027 h70
  text "C" at 13580,1027 h70
  text "11000 (mil)" at 5209.09,-135.99 h60
  text "D" at -1220,-1343 h70
  text "D" at 13580,-1343 h70
  text "ENGINEER:" at 9055,-1440 h45
  text "TITLE:" at 10555,-1440 h45
  text "Fred Keske" at 9505,-1540 h70
  text "Safety" at 11105,-1690 h200
  text "DATE:" at 9055,-1740 h45
  text ".PRINT_DATE" at 9505,-1840 h70
  text "FILE NAME:" at 9055,-2040 h45
  text "PART NO.:" at 10555,-2040 h45
  text "REV:" at 11955,-2040 h45
  text "SCALE:" at 12655,-2040 h45
  text ".PCB_FILE_NAME_NO_PATH" at 9455,-2140 h70
  text "TCS3-Safety" at 10905,-2140 h70
  text "-" at 12255,-2140 h70
  text ".Print_Scale" at 12755,-2140 h70
  text "1" at -63.66,-2375 h70
  text "2" at 2432,-2375 h70
  text "3" at 4921.34,-2375 h70
  text "4" at 7428.01,-2375 h70
  text "5" at 9927,-2375 h70
  text "6" at 12432,-2375 h70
